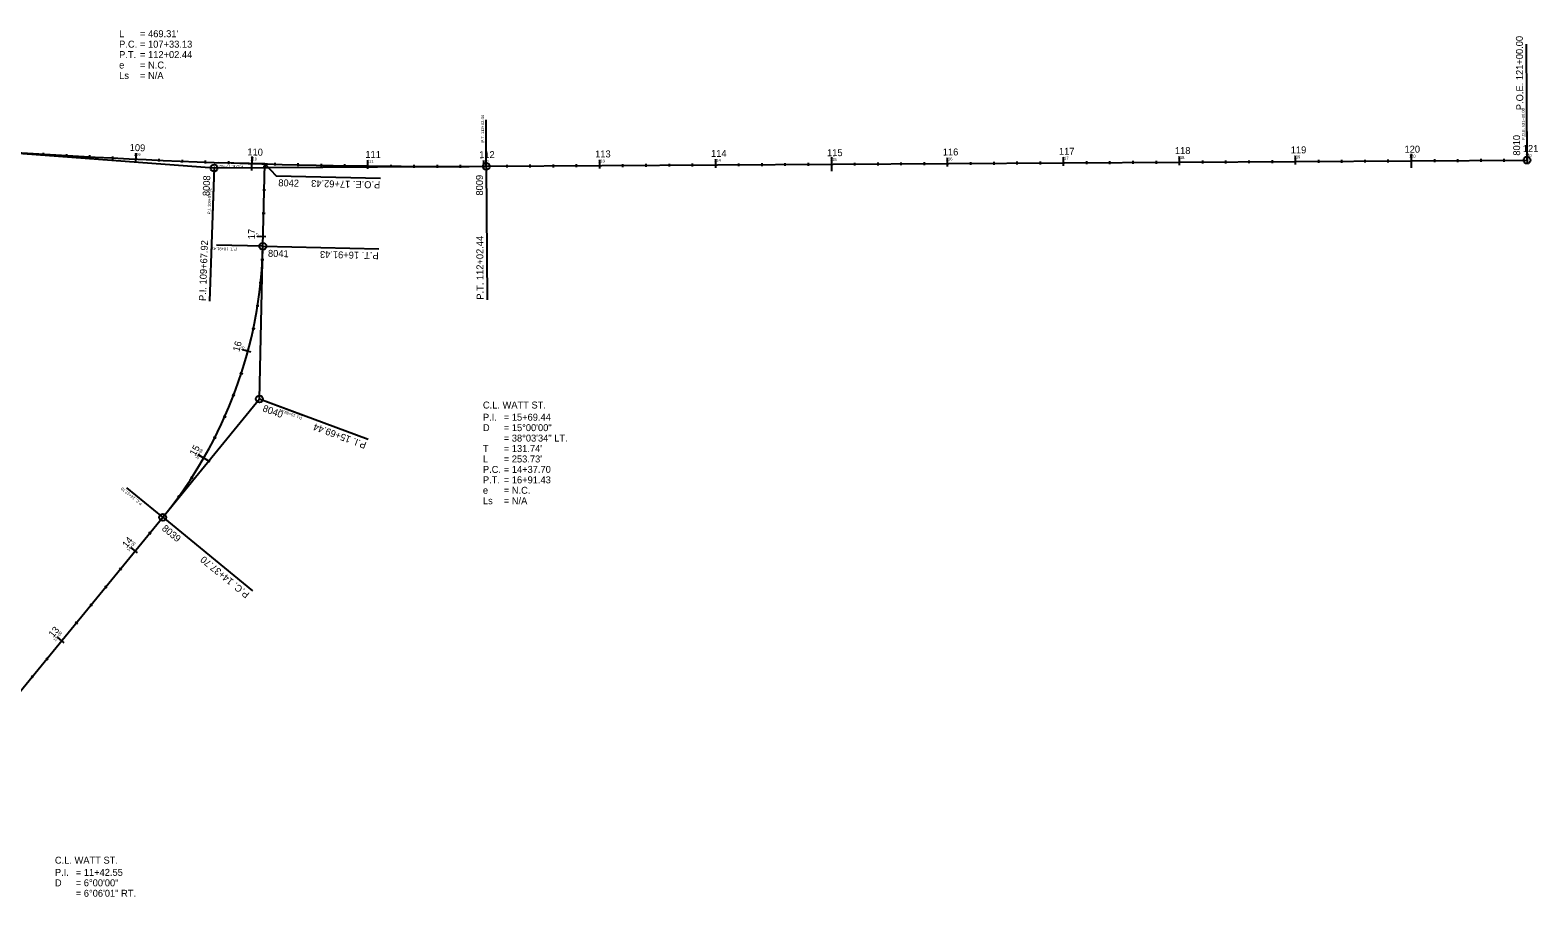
# Model space of a CAD drawing. Extents: x 1708585 to 1714116, y 541444 to 545437.
# Drawn here: x 1712816 to 1714116, y 543637 to 544384 of the extents above; entities that cross this region are included whole.
import ezdxf

# ---------------------------------------------------------------- set-up
doc = ezdxf.new("R2010")
doc.units = 0
for name, color, linetype in [('CL_Highway_1', 7, 'Continuous'), ('CL_Highway_1_40_PText', 7, 'Continuous'), ('CL_Highway_1_40_Sta', 7, 'Continuous'), ('CL_Highway_1_PText', 7, 'Continuous'), ('CL_Highway_1_Sta', 7, 'Continuous'), ('CL_Highway_1_Sta_Minor_Text', 7, 'Continuous'), ('CL_Highway_1_Tangent', 7, 'Continuous'), ('CL_XS_1', 7, 'Continuous'), ('CL_XS_1_40_PText', 7, 'Continuous'), ('CL_XS_1_40_Sta', 7, 'Continuous'), ('CL_XS_1_PText', 7, 'Continuous'), ('CL_XS_1_Sta', 7, 'Continuous'), ('CL_XS_1_Sta_Minor_Text', 7, 'Continuous'), ('CL_XS_1_Tangent', 7, 'Continuous'), ('CurveData_100', 7, 'Continuous'), ('Point_CL_Highway_1', 7, 'Continuous'), ('Point_CL_XS_1', 7, 'Continuous'), ('Point_Number', 7, 'Continuous')]:
    doc.layers.add(name, color=color, linetype=linetype)

msp = doc.modelspace()

# ---------------------------------------------------------------- linework, layer by layer
at = {"layer": 'CL_Highway_1'}
msp.add_line((1713209.5, 544266.5), (1714107.1, 544271.8), dxfattribs=at)
msp.add_arc((1713175.6, 549996), 5729.6, 265.6462, 270.3393, dxfattribs=at)
at = {"layer": 'CL_Highway_1_40_PText'}
for points in [[(1713209.5, 544266.5), (1713209.3, 544306.5)], [(1714107.1, 544271.8), (1714106.9, 544311.8)], [(1712974.8, 544265.1), (1712973.4, 544225.1)]]:
    msp.add_lwpolyline(points, dxfattribs=at)
at = {"layer": 'CL_Highway_1_40_Sta'}
for points in [[(1712827.4, 544278.2), (1712827.2, 544275.8)], [(1712847.4, 544277.1), (1712847.2, 544274.6)], [(1712867.3, 544276), (1712867.2, 544273.5)], [(1712887.3, 544274.9), (1712887.2, 544272.4)], [(1712907.3, 544275.2), (1712907.1, 544270.2)], [(1712927.2, 544273), (1712927.1, 544270.5)], [(1712947.2, 544272.2), (1712947.1, 544269.7)], [(1712967.2, 544271.4), (1712967.1, 544268.9)], [(1712987.2, 544270.8), (1712987.1, 544268.3)], [(1713007.2, 544271.4), (1713007.1, 544266.4)], [(1713027.2, 544269.6), (1713027.1, 544267.1)], [(1713047.1, 544269.1), (1713047.1, 544266.6)], [(1713067.1, 544268.7), (1713067.1, 544266.2)], [(1713087.1, 544268.3), (1713087.1, 544265.8)], [(1713107.1, 544269.3), (1713107.1, 544264.3)], [(1713127.1, 544267.9), (1713127.1, 544265.4)], [(1713147.1, 544267.7), (1713147.1, 544265.2)], [(1713167.1, 544267.7), (1713167.1, 544265.2)], [(1713187.1, 544267.7), (1713187.1, 544265.2)], [(1713207.1, 544269), (1713207.1, 544264)], [(1713227.1, 544267.9), (1713227.1, 544265.4)], [(1713247.1, 544268), (1713247.1, 544265.5)], [(1713267.1, 544268.1), (1713267.1, 544265.6)], [(1713287.1, 544268.2), (1713287.1, 544265.7)], [(1713307.1, 544269.6), (1713307.1, 544264.6)], [(1713327.1, 544268.4), (1713327.1, 544265.9)], [(1713347.1, 544268.6), (1713347.1, 544266.1)], [(1713367.1, 544268.7), (1713367.1, 544266.2)], [(1713387.1, 544268.8), (1713387.1, 544266.3)], [(1713407.1, 544270.2), (1713407.1, 544265.2)], [(1713427.1, 544269), (1713427.1, 544266.5)], [(1713447.1, 544269.2), (1713447.1, 544266.7)], [(1713467.1, 544269.3), (1713467.1, 544266.8)], [(1713487.1, 544269.4), (1713487.1, 544266.9)], [(1713507.1, 544270.8), (1713507.1, 544265.8)], [(1713527.1, 544269.6), (1713527.1, 544267.1)], [(1713547.1, 544269.8), (1713547.1, 544267.3)], [(1713567.1, 544269.9), (1713567.1, 544267.4)], [(1713587.1, 544270), (1713587.1, 544267.5)], [(1713607.1, 544271.4), (1713607.1, 544266.4)], [(1713627.1, 544270.2), (1713627.1, 544267.7)], [(1713647.1, 544270.3), (1713647.1, 544267.8)], [(1713667.1, 544270.5), (1713667.1, 544268)], [(1713687.1, 544270.6), (1713687.1, 544268.1)], [(1713707.1, 544271.9), (1713707.1, 544266.9)], [(1713727.1, 544270.8), (1713727.1, 544268.3)], [(1713747.1, 544270.9), (1713747.1, 544268.4)], [(1713767.1, 544271.1), (1713767.1, 544268.6)], [(1713787.1, 544271.2), (1713787.1, 544268.7)], [(1713807.1, 544272.5), (1713807.1, 544267.5)], [(1713827.1, 544271.4), (1713827.1, 544268.9)], [(1713847.1, 544271.5), (1713847.1, 544269)], [(1713867.1, 544271.6), (1713867.1, 544269.1)], [(1713887.1, 544271.8), (1713887.1, 544269.3)], [(1713907.1, 544273.1), (1713907.1, 544268.1)], [(1713927.1, 544272), (1713927.1, 544269.5)], [(1713947.1, 544272.1), (1713947.1, 544269.6)], [(1713967.1, 544272.2), (1713967.1, 544269.7)], [(1713987.1, 544272.4), (1713987.1, 544269.9)], [(1714007.1, 544273.7), (1714007.1, 544268.7)], [(1714027.1, 544272.6), (1714027.1, 544270.1)], [(1714047.1, 544272.7), (1714047.1, 544270.2)], [(1714067.1, 544272.8), (1714067.1, 544270.3)], [(1714087.1, 544272.9), (1714087.1, 544270.4)], [(1714107.1, 544274.3), (1714107.1, 544269.3)]]:
    msp.add_lwpolyline(points, dxfattribs=at)
at = {"layer": 'CL_Highway_1_PText'}
for points in [[(1714107.1, 544271.8), (1714106.5, 544371.8)], [(1712974.8, 544265.1), (1712970.7, 544150.2)], [(1713209.5, 544266.5), (1713210.2, 544151.5)]]:
    msp.add_lwpolyline(points, dxfattribs=at)
at = {"layer": 'CL_Highway_1_Sta'}
for points in [[(1712907.4, 544277.7), (1712907.2, 544272.7)], [(1714007.1, 544277.2), (1714007.1, 544265.2)], [(1714107.1, 544277.8), (1714107.1, 544271.8)], [(1713007.3, 544274.9), (1713007, 544262.9)], [(1713107.2, 544271.8), (1713107.1, 544266.8)], [(1713207.1, 544271.5), (1713207.1, 544266.5)], [(1713307.1, 544272.1), (1713307.1, 544267.1)], [(1713407.1, 544272.7), (1713407.1, 544267.7)], [(1713507.1, 544274.3), (1713507.1, 544262.3)], [(1713607.1, 544273.9), (1713607.1, 544268.9)], [(1713707.1, 544274.4), (1713707.1, 544269.4)], [(1713807.1, 544275), (1713807.1, 544270)], [(1713907.1, 544275.6), (1713907.1, 544270.6)]]:
    msp.add_lwpolyline(points, dxfattribs=at)
at = {"layer": 'CL_Highway_1_Tangent'}
for p, q in [((1712740.7, 544282.9), (1712974.8, 544265.1)), ((1712974.8, 544265.1), (1713209.5, 544266.5))]:
    msp.add_line(p, q, dxfattribs=at)
at = {"layer": 'CL_XS_1'}
for p, q in [((1713016.8, 544197.6), (1713018.4, 544268.6)), ((1712775.6, 543774.9), (1712930.5, 543963.9))]:
    msp.add_line(p, q, dxfattribs=at)
msp.add_arc((1712635, 544206), 382, 320.6814, 358.7408, dxfattribs=at)
at = {"layer": 'CL_XS_1_40_PText'}
for points in [[(1713018.4, 544268.6), (1712978.4, 544269.4)], [(1713016.8, 544197.6), (1712976.9, 544198.5)], [(1713013.9, 544065.9), (1713051.5, 544052)], [(1712930.5, 543963.9), (1712899.5, 543989.3)]]:
    msp.add_lwpolyline(points, dxfattribs=at)
at = {"layer": 'CL_XS_1_40_Sta'}
for points in [[(1713015.9, 544268.6), (1713020.9, 544268.5)], [(1713017.1, 544266.2), (1713019.6, 544266.1)], [(1713016.7, 544246.2), (1713019.2, 544246.1)], [(1713016.2, 544226.2), (1713018.7, 544226.1)], [(1713014.5, 544206.2), (1713019.5, 544206.1)], [(1713015.2, 544186.2), (1713017.7, 544186.1)], [(1713013.6, 544166.3), (1713016.1, 544166.1)], [(1713011, 544146.6), (1713013.5, 544146.2)], [(1713007.4, 544127), (1713009.8, 544126.5)], [(1713001.5, 544107.9), (1713006.4, 544106.6)], [(1712997.1, 544088.5), (1712999.5, 544087.7)], [(1712990.5, 544069.7), (1712992.8, 544068.8)], [(1712982.8, 544051.3), (1712985.1, 544050.3)], [(1712974.3, 544033.3), (1712976.5, 544032.1)], [(1712963.7, 544016.4), (1712968, 544013.9)], [(1712954.4, 543998.8), (1712956.5, 543997.4)], [(1712943.1, 543982.3), (1712945.1, 543980.9)], [(1712930.9, 543966.5), (1712932.9, 543964.9)], [(1712918.3, 543951), (1712920.2, 543949.5)], [(1712904.6, 543936.4), (1712908.5, 543933.2)], [(1712892.9, 543920.1), (1712894.9, 543918.5)], [(1712880.3, 543904.6), (1712882.2, 543903)], [(1712867.6, 543889.1), (1712869.5, 543887.6)], [(1712854.9, 543873.7), (1712856.9, 543872.1)], [(1712841.3, 543859), (1712845.2, 543855.8)], [(1712829.6, 543842.7), (1712831.5, 543841.1)], [(1712816.9, 543827.3), (1712818.8, 543825.7)]]:
    msp.add_lwpolyline(points, dxfattribs=at)
at = {"layer": 'CL_XS_1_PText'}
for points in [[(1713018.4, 544268.6), (1713028.2, 544258.3), (1713118.2, 544256.4)], [(1713016.8, 544197.6), (1713116.8, 544195.4)], [(1713013.9, 544065.9), (1713107.7, 544031.2)], [(1712930.5, 543963.9), (1713007.8, 543900.6)]]:
    msp.add_lwpolyline(points, dxfattribs=at)
at = {"layer": 'CL_XS_1_Sta'}
for points in [[(1713012, 544206.3), (1713017, 544206.1)], [(1712999.1, 544108.6), (1713004, 544107.3)], [(1712960.7, 544018.1), (1712971, 544012.1)], [(1712902.7, 543937.9), (1712906.6, 543934.8)], [(1712839.4, 543860.6), (1712843.2, 543857.4)]]:
    msp.add_lwpolyline(points, dxfattribs=at)
at = {"layer": 'CL_XS_1_Tangent'}
for p, q in [((1713013.9, 544065.9), (1713016.8, 544197.6)), ((1712930.5, 543963.9), (1713013.9, 544065.9))]:
    msp.add_line(p, q, dxfattribs=at)
at = {"layer": 'Point_CL_Highway_1'}
for centre in [(1712974.8, 544265.1), (1713209.5, 544266.5), (1714107.1, 544271.8)]:
    msp.add_circle(centre, 3, dxfattribs=at)
at = {"layer": 'Point_CL_XS_1'}
for centre in [(1713016.8, 544197.6), (1713013.9, 544065.9), (1712930.5, 543963.9)]:
    msp.add_circle(centre, 3, dxfattribs=at)

# ---------------------------------------------------------------- texts
at = {"layer": 'CL_Highway_1_40_PText'}
for s, rotation, p in [('P.O.E. 121+00.00', 90.3393, (1714105.2, 544289.1)), ('P.T. 112+02.44', 90.3393, (1713207.7, 544287)), ('P.I. 109+67.92', 87.9927, (1712971.6, 544225.2))]:
    msp.add_text(s, height=2.5, rotation=rotation, dxfattribs=at).set_placement(p)
at = {"layer": 'CL_Highway_1_40_Sta'}
for s, rotation, p in [('109', 357.3149, (1712905.5, 544275.5)), ('120', 0.3393, (1714005.2, 544274)), ('120', 0.3393, (1714105.2, 544274.6)), ('110', 358.3149, (1713005.9, 544271.7)), ('111', 359.3149, (1713106.5, 544269.6)), ('112', 0.3149, (1713205.9, 544269.2)), ('113', 0.3393, (1713305.9, 544269.8)), ('114', 0.3393, (1713405.9, 544270.4)), ('115', 0.3393, (1713505.9, 544271)), ('116', 0.3393, (1713605.8, 544271.6)), ('117', 0.3393, (1713705.9, 544272.2)), ('118', 0.3393, (1713805.8, 544272.8)), ('119', 0.3393, (1713905.8, 544273.4))]:
    msp.add_text(s, height=2.5, rotation=rotation, dxfattribs=at).set_placement(p)
at = {"layer": 'CL_Highway_1_PText'}
for s, rotation, p in [('P.O.E. 121+00.00', 90.3393, (1714103.8, 544314.9)), ('P.I. 109+67.92', 87.9927, (1712967.7, 544150.3)), ('P.T. 112+02.44', 90.3393, (1713207.2, 544151.5))]:
    msp.add_text(s, height=6, rotation=rotation, dxfattribs=at).set_placement(p)
at = {"layer": 'CL_Highway_1_Sta'}
for s, rotation, p in [('110', 358.3149, (1713003.4, 544276)), ('115', 0.3393, (1713503.4, 544275.2)), ('120', 0.3393, (1714001.4, 544278.2))]:
    msp.add_text(s, height=6, rotation=rotation, dxfattribs=at).set_placement(p)
at = {"layer": 'CL_Highway_1_Sta_Minor_Text'}
for s, rotation, p in [('109', 357.3149, (1712901.9, 544279.9)), ('111', 359.3149, (1713105.2, 544273.8)), ('112', 0.3149, (1713203.4, 544273.5)), ('113', 0.3393, (1713303.4, 544274.1)), ('114', 0.3393, (1713403.4, 544274.6)), ('116', 0.3393, (1713603.2, 544275.8)), ('117', 0.3393, (1713703.4, 544276.4)), ('118', 0.3393, (1713803.4, 544277)), ('119', 0.3393, (1713903.3, 544277.6)), ('121', 0.3393, (1714103.4, 544278.8))]:
    msp.add_text(s, height=6, rotation=rotation, dxfattribs=at).set_placement(p)
at = {"layer": 'CL_XS_1_40_PText'}
for s, rotation, p in [('P.O.E. 17+62.43', 178.7408, (1712999.9, 544267.2)), ('P.T. 16+91.43', 178.7408, (1712994.4, 544196.3)), ('P.I. 15+69.44', 159.7111, (1713050.9, 544050.4)), ('P.C. 14+37.70', 140.6814, (1712912.9, 543976))]:
    msp.add_text(s, height=2.5, rotation=rotation, dxfattribs=at).set_placement(p)
at = {"layer": 'CL_XS_1_40_Sta'}
for s, rotation, p in [('17', 88.7408, (1713013.3, 544205.3)), ('16', 75.0264, (1713000.1, 544107.3)), ('15+00', 60.0264, (1712960.7, 544013.7)), ('14+00', 50.6814, (1712901.3, 543934.2)), ('13+00', 50.6814, (1712837.9, 543856.8))]:
    msp.add_text(s, height=2.5, rotation=rotation, dxfattribs=at).set_placement(p)
at = {"layer": 'CL_XS_1_PText'}
for s, rotation, p in [('P.O.E. 17+62.43', 178.7408, (1713118.1, 544253.4)), ('P.T. 16+91.43', 178.7408, (1713116.8, 544192.4)), ('P.I. 15+69.44', 159.7111, (1713106.7, 544028.4)), ('P.C. 14+37.70', 140.6814, (1713005.9, 543898.3))]:
    msp.add_text(s, height=6, rotation=rotation, dxfattribs=at).set_placement(p)
at = {"layer": 'CL_XS_1_Sta'}
msp.add_text('15', height=6, rotation=60.0264, dxfattribs=at).set_placement((1712958.4, 544016.3))
at = {"layer": 'CL_XS_1_Sta_Minor_Text'}
for s, rotation, p in [('17', 88.7408, (1713010, 544203.6)), ('16', 75.0264, (1712996.5, 544106.3)), ('14', 50.6814, (1712899.5, 543937.1)), ('13', 50.6814, (1712836.1, 543859.8))]:
    msp.add_text(s, height=6, rotation=rotation, dxfattribs=at).set_placement(p)
at = {"layer": 'CurveData_100'}
for s, p in [('L', (1712892.9, 544377.8)), ("= 469.31'", (1712910.9, 544377.8)), ('P.C.', (1712892.9, 544368.8)), ('= 107+33.13', (1712910.9, 544368.8)), ('e', (1712892.9, 544350.8)), ('P.T.', (1712892.9, 544359.8)), ('= 112+02.44', (1712910.9, 544359.8)), ('= N.C.', (1712910.9, 544350.8)), ('Ls', (1712892.9, 544341.8)), ('= N/A', (1712910.9, 544341.8)), ('C.L. WATT ST.', (1713206.6, 544057.7)), ('P.I.', (1713206.6, 544047.2)), ('D', (1713206.6, 544038.2)), ('= 15+69.44', (1713224.6, 544047.2)), ('= 15%%d00\'00"', (1713224.6, 544038.2)), ('= 38%%d03\'34" LT.', (1713224.6, 544029.2)), ('T', (1713206.6, 544020.2)), ('L', (1713206.6, 544011.2)), ("= 131.74'", (1713224.6, 544020.2)), ("= 253.73'", (1713224.6, 544011.2)), ('P.C.', (1713206.6, 544002.2)), ('= 14+37.70', (1713224.6, 544002.2)), ('P.T.', (1713206.6, 543993.2)), ('= 16+91.43', (1713224.6, 543993.2)), ('= N.C.', (1713224.6, 543984.2)), ('e', (1713206.6, 543984.2)), ('Ls', (1713206.6, 543975.2)), ('= N/A', (1713224.6, 543975.2)), ('C.L. WATT ST.', (1712837.5, 543665.3)), ('P.I.', (1712837.5, 543654.8)), ('= 11+42.55', (1712855.5, 543654.8)), ('D', (1712837.5, 543645.8)), ('= 6%%d00\'00"', (1712855.5, 543645.8)), ('= 6%%d06\'01" RT.', (1712855.5, 543636.8))]:
    msp.add_text(s, height=6, dxfattribs=at).set_placement(p)
at = {"layer": 'Point_Number'}
for s, rotation, p in [('8010', 90.3393, (1714101.1, 544275.7)), ('8008', 87.9927, (1712970.9, 544240.7)), ('8042', 358.7408, (1713030.1, 544249.3)), ('8009', 90.3393, (1713206.7, 544241.3)), ('8041', 358.7408, (1713021.2, 544188.5)), ('8040', 339.7111, (1713016.1, 544055.5)), ('8039', 320.6814, (1712929.2, 543953.4))]:
    msp.add_text(s, height=6, rotation=rotation, dxfattribs=at).set_placement(p)

doc.saveas('drawing.dxf')
